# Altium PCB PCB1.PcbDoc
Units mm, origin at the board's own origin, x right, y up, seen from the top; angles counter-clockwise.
Board outline 89.28 x 76.58 mm, 2 copper layers (Top Layer, Bottom Layer); 90 components, 100 nets, 288 pads, 103 vias.
Unrouted connection lines stored in the file: 1.
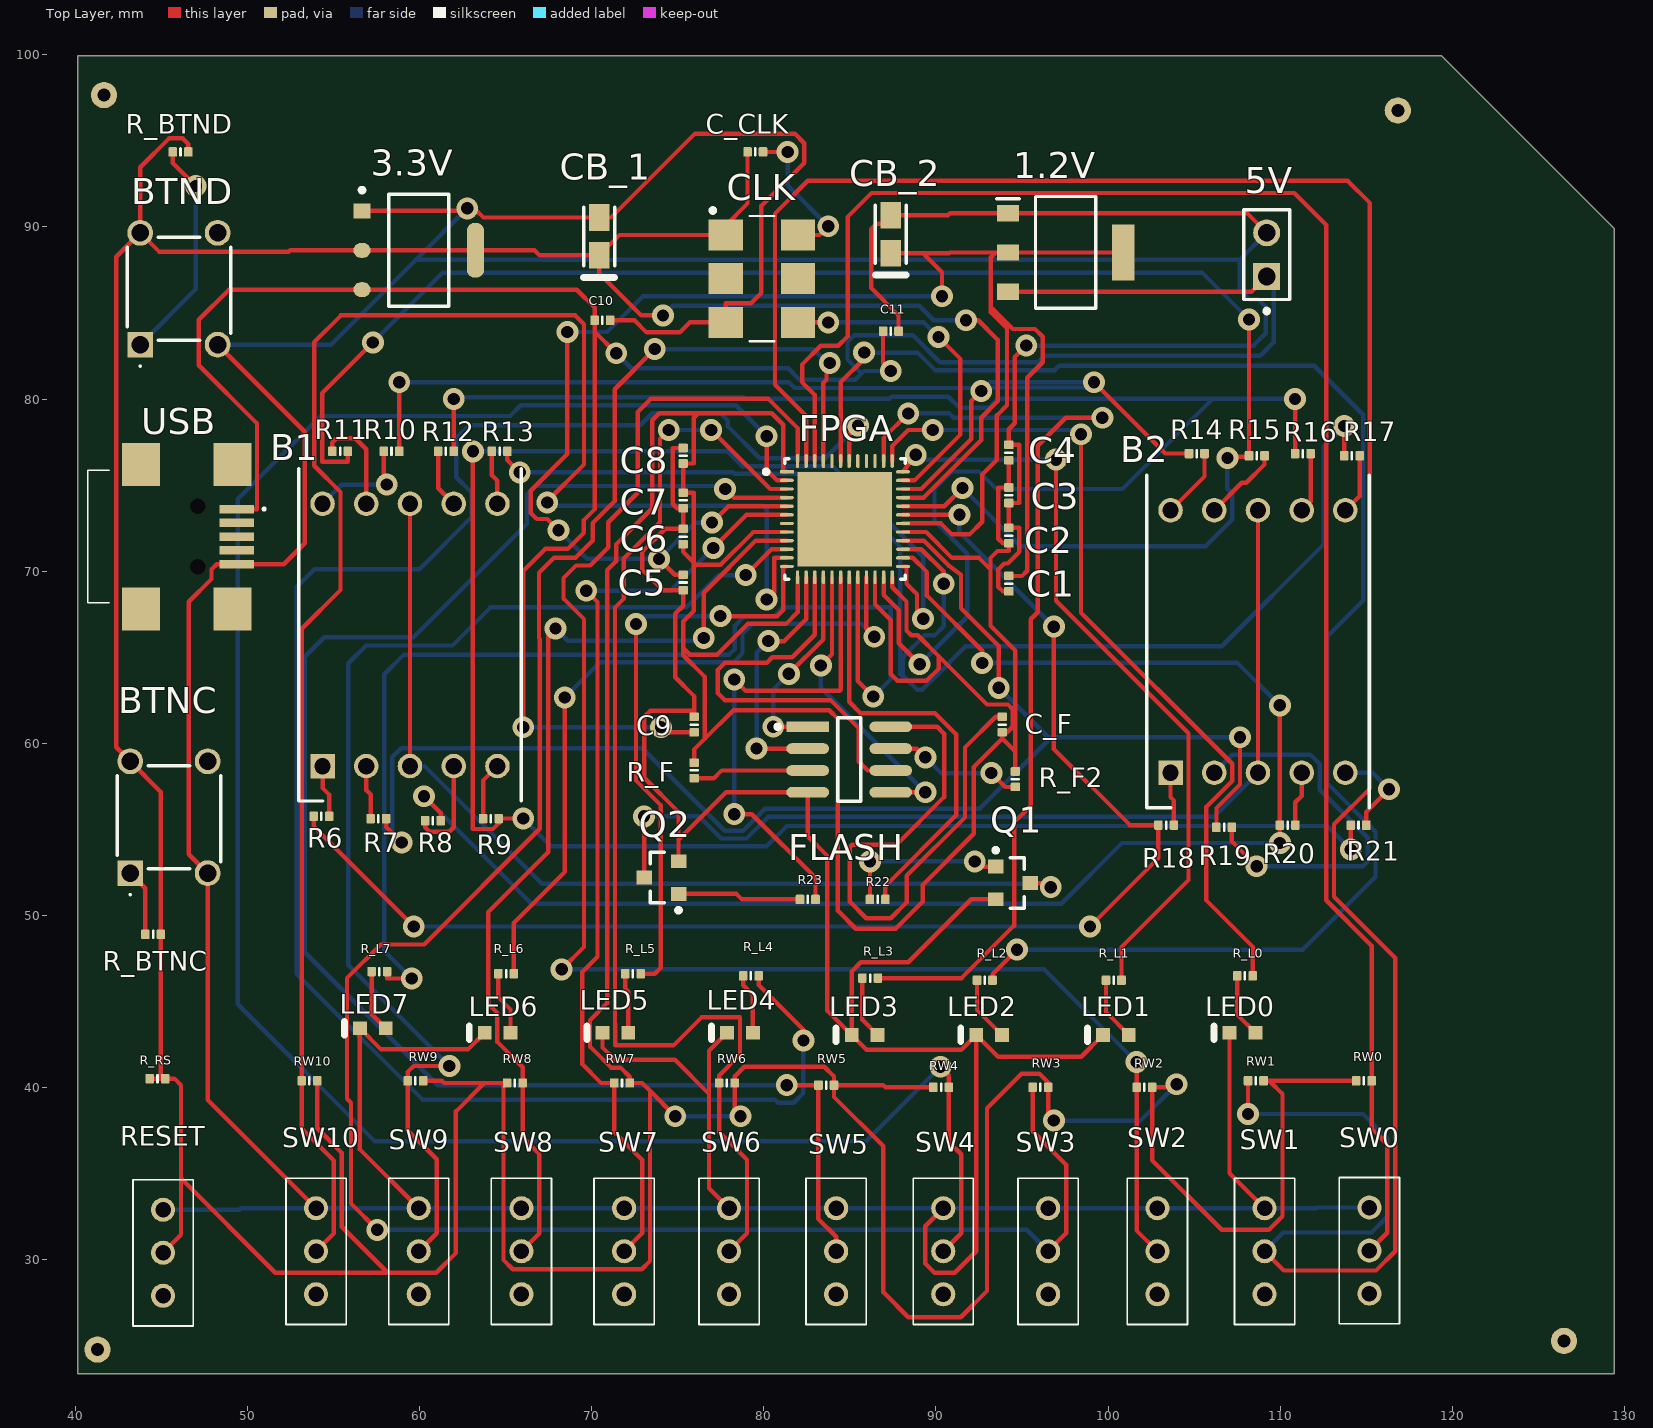
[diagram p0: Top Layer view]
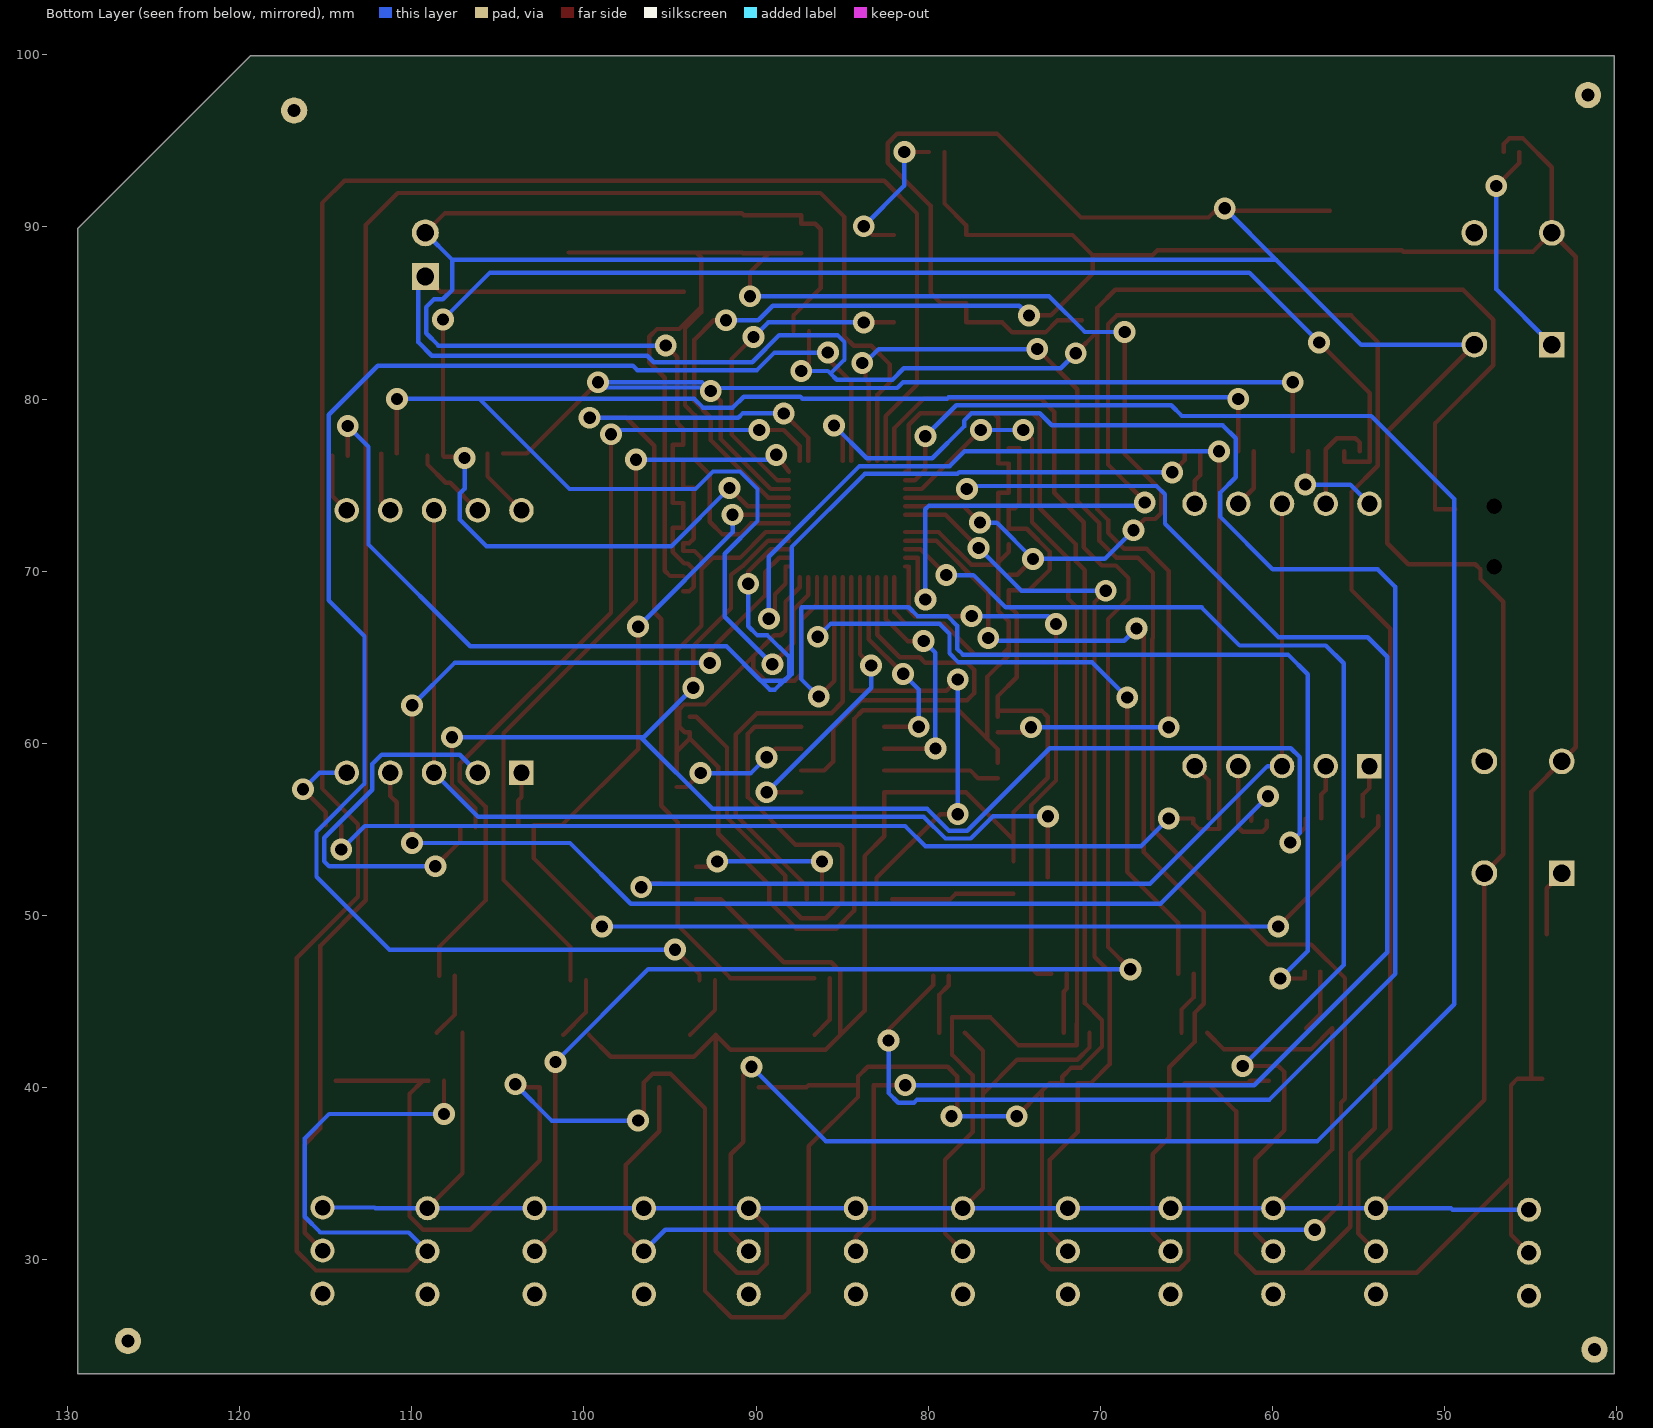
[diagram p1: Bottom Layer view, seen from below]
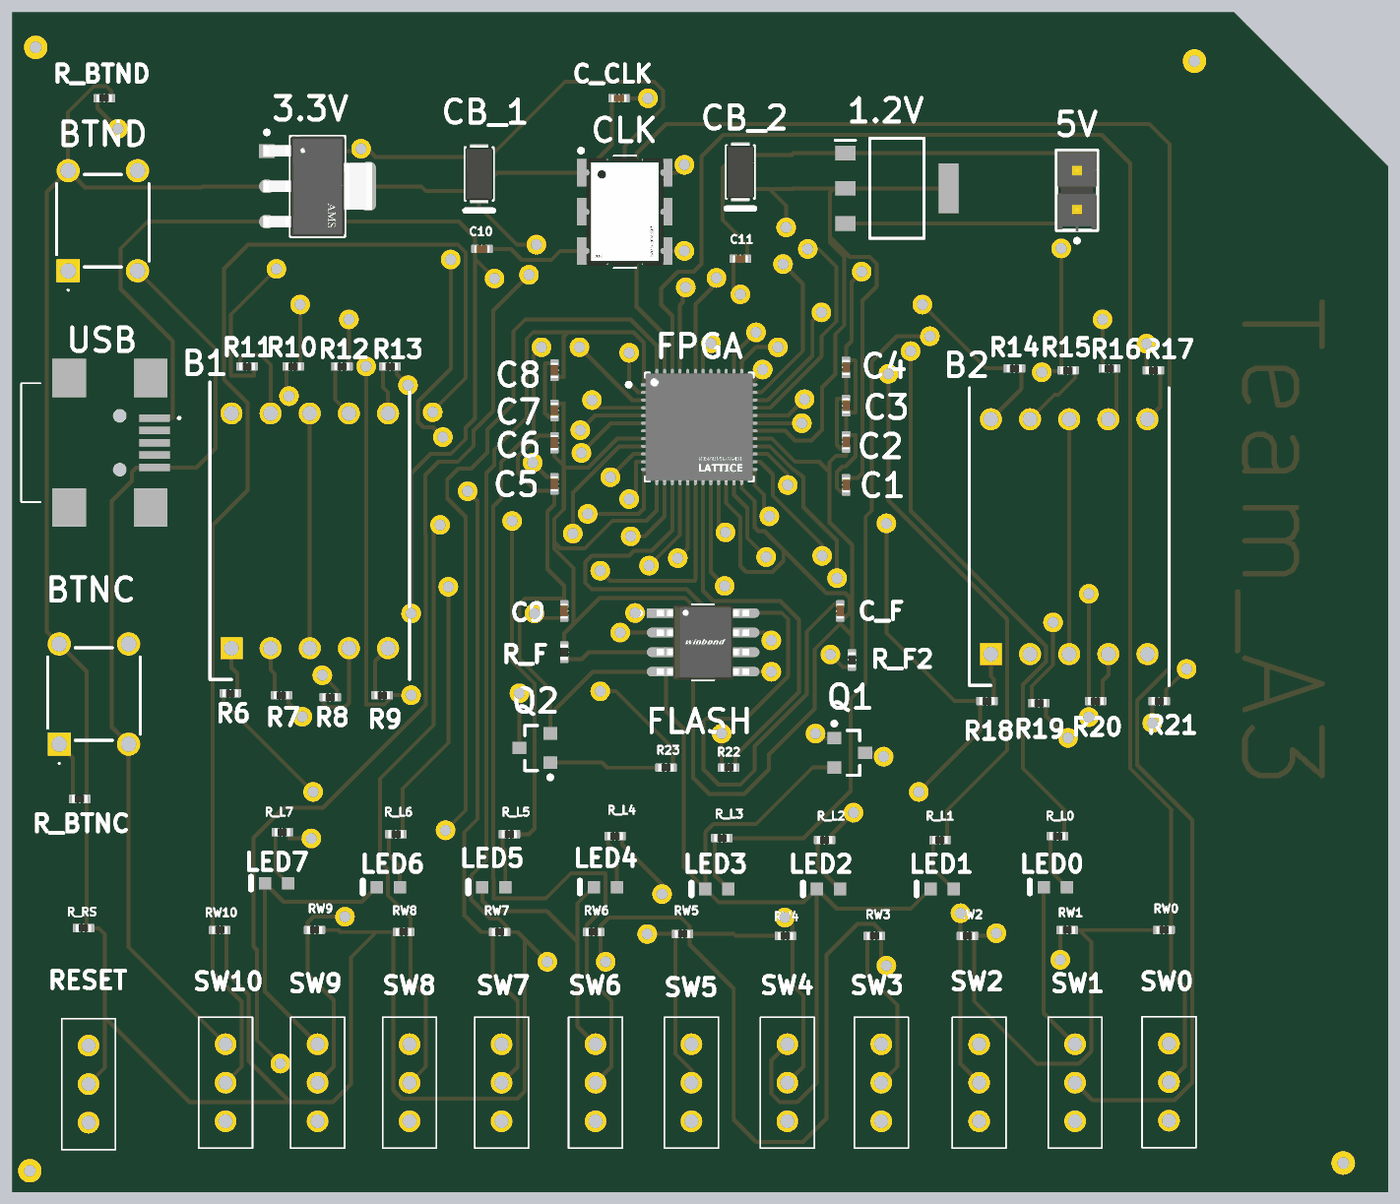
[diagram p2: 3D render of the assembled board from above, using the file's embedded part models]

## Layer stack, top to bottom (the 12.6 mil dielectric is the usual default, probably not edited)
Top Solder: solder mask 0.0102, Solder Resist, Dk 3.5
Top Layer: signal copper 0.0356
Dielectric 1: dielectric 0.32, FR-4, Dk 4.8
Bottom Layer: signal copper 0.0356
Bottom Solder: solder mask 0.0102, Solder Resist, Dk 3.5

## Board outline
40.132,23.368 40.132,99.949 119.38,99.949 129.413,89.916 129.413,23.368

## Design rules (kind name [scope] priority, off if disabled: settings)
Clearance [All] p1: gap=0.2 ignorepadtopadclearanceinfootprint=TRUE
HoleToHoleClearance [All] p1: gap=0.1 allowstackedmicrovias=TRUE
MinimumSolderMaskSliver [All] p1: minsoldermaskwidth=0.1
PolygonConnect [All] p1: connectstyle=Relief reliefconductorwidth=0.254 reliefentries=4 polygonreliefangle="90 Angle" airgapwidth=0.254
RoutingVias [All] p1: holewidth=0.711 width=1.27 viastyle="Through Hole" minholewidth=0.711 minwidth=1.27 maxholewidth=0.711 maxwidth=1.27
SilkToSilkClearance [All] p1 off: silktosilkclearance=0.254
SilkToSolderMaskClearance [IsPad] p1 off: minsilkscreentomaskgap=0.254 clearancetoexposedcopper=TRUE
SolderMaskExpansion [All] p1: expansion=0 istentingtop=FALSE
SupplyNets "Schematic Supply Nets_4" [InNet('VCC_1.2V')] p1: voltage=0.000
SupplyNets "Schematic Supply Nets_2" [InNet('GND')] p2: voltage=0.000
SupplyNets "Schematic Supply Nets" [InNet('VCC_3.3V')] p3: voltage=0.000
Width [All] p1: maxlimit=0.254 minlimit=0.254 preferedwidth=0.254
26 further rules are at their usual default settings.

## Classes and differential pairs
component class "Flash Memory_SPI": C_F FLASH R_F R_F2
component class Power_Supply: 1.2V 3.3V 5V C9 C10 C11 CB_1 CB_2 USB
component class FPGA: C1 C2 C3 C4 C5 C6 C7 C8 C_CLK CLK FPGA
component class 7Seg_&_Keypad: B1 B2 BTNC BTND LED0 LED1 LED2 LED3 LED4 LED5 LED6 LED7 Q1 Q2 R6 R7 R8 R9 R10 R11 R12 R13 R14 R15 R16 R17 R18 R19 R20 R21 R22 R23 R_BTNC R_BTND R_L0 R_L1 R_L2 R_L3 R_L4 R_L5 R_L6 R_L7 R_RS RESET RW0 RW1 RW2 RW3 RW4 RW5 RW6 RW7 RW8 RW9 RW10 SW0 SW1 SW2 SW3 SW4 SW5 SW6 SW7 SW8 SW9 SW10

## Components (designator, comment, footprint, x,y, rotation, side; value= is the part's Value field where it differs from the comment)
1.2V "AMS1117-1.2" SOT229P700X180-4N 97.536,88.519 r0 top
3.3V "AMS1117-3.3" FP-AMS1117-IPC_C 59.944,88.646 r0 top
5V "TSW-102-12-T-S" FP-TSW-102-12-T-S-MFG 109.22,88.392 r90 top
B1 "SC56-11EWA" DIPS1524W75P254L1270H825Q10N 54.356,58.674 r90 top
B2 "SC56-11EWA" DIPS1524W75P254L1270H825Q10N 103.632,58.293 r90 top
BTNC "1301.9301" 13019301 43.18,52.451 r90 top
BTND "1301.9301" 13019301 43.76,83.162 r90 top
C1 "Capacitor 100nF +/-20% 50V 0402" CAPC0402(1005)60_L 94.234,69.273 r270 top value=100nF
C2 "Capacitor 100nF +/-20% 50V 0402" CAPC0402(1005)60_L 94.234,72.067 r90 top value=100nF
C3 "Capacitor 100nF +/-20% 50V 0402" CAPC0402(1005)60_L 94.234,74.411 r270 top value=100nF
C4 "Capacitor 100nF +/-20% 50V 0402" CAPC0402(1005)60_L 94.234,76.893 r90 top value=100nF
C5 "Capacitor 100nF +/-20% 50V 0402" CAPC0402(1005)60_L 75.311,69.342 r270 top value=100nF
C6 "Capacitor 100nF +/-20% 50V 0402" CAPC0402(1005)60_L 75.311,72.009 r90 top value=100nF
C7 "Capacitor 100nF +/-20% 50V 0402" CAPC0402(1005)60_L 75.311,74.11 r270 top value=100nF
C8 "Capacitor 100nF +/-20% 50V 0402" CAPC0402(1005)60_L 75.311,76.708 r90 top value=100nF
C9 "Capacitor 100nF +/-20% 50V 0402" CAPC0402(1005)60_L 75.946,61.087 r90 top value=100nF
C10 "Capacitor 100nF +/-20% 50V 0402" CAPC0402(1005)60_L 70.612,84.582 r0 top value=100nF
C11 "Capacitor 100nF +/-20% 50V 0402" CAPC0402(1005)60_L 87.376,83.947 r0 top value=100nF
C_CLK "Capacitor 100nF +/-20% 25V 0402" CAPC0402(1005)60_L 79.502,94.361 r0 top value=100nF
C_F "Capacitor 100nF +/-20% 50V 0402" CAPC0402(1005)60_L 93.853,61.087 r90 top value=100nF
CB_1 "TAJA475K016RNJ" AVX-TAJ-A-2_L 70.427,89.451 r90 top value=4.7µF
CB_2 "TAJA475K016RNJ" AVX-TAJ-A-2_L 87.376,89.578 r90 top value=4.7µF
CLK "XLH735012.000000I" JU6_MFG 79.883,86.995 r0 top
FLASH "W25Q16JVSNIQ TR" FP-W25Q16JVSNIQ_TR-IPC_A 84.96,59.055 r0 top
FPGA "iCE40UP5K-SG48I" FP-QFN-48-IPC_C 84.709,73.025 r0 top
LED0 "19-217/Y5C-AM1N1VY/3T" EVRL-0603-2_V 107.811,43.18 r180 top
LED1 "19-217/Y5C-AM1N1VY/3T" EVRL-0603-2_V 100.457,43.053 r180 top
LED2 "19-217/Y5C-AM1N1VY/3T" EVRL-0603-2_V 93.091,43.053 r180 top
LED3 "19-217/Y5C-AM1N1VY/3T" EVRL-0603-2_V 85.852,43.053 r180 top
LED4 "19-217/Y5C-AM1N1VY/3T" EVRL-0603-2_V 78.613,43.18 r180 top
LED5 "19-217/Y5C-AM1N1VY/3T" EVRL-0603-2_V 71.374,43.18 r180 top
LED6 "19-217/Y5C-AM1N1VY/3T" EVRL-0603-2_V 64.528,43.18 r180 top
LED7 "19-217/Y5C-AM1N1VY/3T" EVRL-0603-2_V 57.277,43.434 r180 top
Q1 "SBC817-40LT3G" ONSC-SOT-23-3-318-08_V 94.472,51.882 r0 top
Q2 "SBC817-40LT3G" ONSC-SOT-23-3-318-08_V 74.041,52.197 r180 top
R6 "Resistor 330R +/-5 % 0402 63 mW" RESC0402(1005)_L 54.287,55.753 r0 top value=330
R7 "Resistor 330R +/-5 % 0402 63 mW" RESC0402(1005)_L 57.6,55.626 r180 top value=330
R8 "Resistor 330R +/-5 % 0402 63 mW" RESC0402(1005)_L 60.764,55.499 r180 top value=330
R9 "Resistor 330R +/-5 % 0402 63 mW" RESC0402(1005)_L 64.135,55.626 r180 top value=330
R10 "Resistor 330R +/-5 % 0402 63 mW" RESC0402(1005)_L 58.362,76.962 r0 top value=330
R11 "Resistor 330R +/-5 % 0402 63 mW" RESC0402(1005)_L 55.372,76.962 r0 top value=330
R12 "Resistor 330R +/-5 % 0402 63 mW" RESC0402(1005)_L 61.526,76.962 r0 top value=330
R13 "Resistor 330R +/-5 % 0402 63 mW" RESC0402(1005)_L 64.643,76.962 r0 top value=330
R14 "Resistor 330R +/-5 % 0402 63 mW" RESC0402(1005)_L 105.156,76.835 r180 top value=330
R15 "Resistor 330R +/-5 % 0402 63 mW" RESC0402(1005)_L 108.643,76.708 r180 top value=330
R16 "Resistor 330R +/-5 % 0402 63 mW" RESC0402(1005)_L 111.321,76.835 r180 top value=330
R17 "Resistor 330R +/-5 % 0402 63 mW" RESC0402(1005)_L 114.173,76.708 r180 top value=330
R18 "Resistor 330R +/-5 % 0402 63 mW" RESC0402(1005)_L 103.378,55.245 r0 top value=330
R19 "Resistor 330R +/-5 % 0402 63 mW" RESC0402(1005)_L 106.749,55.118 r0 top value=330
R20 "Resistor 330R +/-5 % 0402 63 mW" RESC0402(1005)_L 110.432,55.245 r0 top value=330
R21 "Resistor 330R +/-5 % 0402 63 mW" RESC0402(1005)_L 114.554,55.245 r0 top value=330
R22 "1KR2J" RESC0402(1005)_L 86.614,50.927 r180 top value=1k
R23 "1KR2J" RESC0402(1005)_L 82.55,50.927 r180 top value=1k
R_BTNC "10KR2F" RESC0402(1005)_L 44.508,48.895 r180 top value=10k
R_BTND "10KR2F" RESC0402(1005)_L 46.101,94.361 r180 top value=10k
R_F "10KR2F" RESC0402(1005)_L 75.946,58.42 r90 top value=10k
R_F2 "10KR2F" RESC0402(1005)_L 94.615,57.912 r90 top value=10k
R_L0 "330R2J" RESC0402(1005)_L 107.95,46.482 r180 top value=330
R_L1 "330R2J" RESC0402(1005)_L 100.33,46.228 r180 top value=330
R_L2 "330R2J" RESC0402(1005)_L 92.837,46.228 r180 top value=330
R_L3 "330R2J" RESC0402(1005)_L 86.175,46.355 r180 top value=330
R_L4 "330R2J" RESC0402(1005)_L 79.248,46.482 r180 top value=330
R_L5 "330R2J" RESC0402(1005)_L 72.39,46.609 r180 top value=330
R_L6 "330R2J" RESC0402(1005)_L 65.024,46.609 r180 top value=330
R_L7 "330R2J" RESC0402(1005)_L 57.658,46.736 r180 top value=330
R_RS "10KR2F" RESC0402(1005)_L 44.762,40.513 r0 top value=10k
RESET "SS12D00G3" SS12D00G3 45.085,30.393 r90 top
RW0 "10KR2F" RESC0402(1005)_L 114.866,40.386 r0 top value=10k
RW1 "10KR2F" RESC0402(1005)_L 108.585,40.386 r180 top value=10k
RW2 "10KR2F" RESC0402(1005)_L 102.108,40.005 r180 top value=10k
RW3 "10KR2F" RESC0402(1005)_L 96.07,40.005 r180 top value=10k
RW4 "10KR2F" RESC0402(1005)_L 90.297,40.005 r0 top value=10k
RW5 "10KR2F" RESC0402(1005)_L 83.624,40.132 r180 top value=10k
RW6 "10KR2F" RESC0402(1005)_L 77.851,40.259 r180 top value=10k
RW7 "10KR2F" RESC0402(1005)_L 71.755,40.259 r180 top value=10k
RW8 "10KR2F" RESC0402(1005)_L 65.532,40.259 r0 top value=10k
RW9 "10KR2F" RESC0402(1005)_L 59.748,40.386 r180 top value=10k
RW10 "10KR2F" RESC0402(1005)_L 53.594,40.386 r180 top value=10k
SW0 "SS12D00G3" SS12D00G3 115.189,30.52 r90 top
SW1 "SS12D00G3" SS12D00G3 109.093,30.48 r90 top
SW2 "SS12D00G3" SS12D00G3 102.87,30.48 r90 top
SW3 "SS12D00G3" SS12D00G3 96.52,30.48 r90 top
SW4 "SS12D00G3" SS12D00G3 90.424,30.48 r90 top
SW5 "SS12D00G3" SS12D00G3 84.201,30.48 r90 top
SW6 "SS12D00G3" SS12D00G3 77.978,30.48 r90 top
SW7 "SS12D00G3" SS12D00G3 71.882,30.48 r90 top
SW8 "SS12D00G3" SS12D00G3 65.913,30.48 r90 top
SW9 "SS12D00G3" SS12D00G3 59.944,30.48 r90 top
SW10 "SS12D00G3" SS12D00G3 53.975,30.48 r90 top
USB "UX60-MB-5ST" UX60MB5ST 45.212,72.009 r270 top

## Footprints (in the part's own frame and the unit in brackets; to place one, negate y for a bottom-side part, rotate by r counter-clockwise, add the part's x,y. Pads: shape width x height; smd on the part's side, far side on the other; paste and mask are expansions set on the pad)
13019301 [mm]
  rect 1.5x1.5 hole 1: 1(0,0)
  round 1.5 hole 1: 2(6.5,0) 3(0,-4.5) 4(6.5,-4.5)
  silkscreen extent -1.3,-5.25 6.25,0.75
AVX-TAJ-A-2_L [mm] "Molded Capacitor, 2-Leads, Body 3.4x1.8mm, IPC High Density"
  rect 1.55x1.2 smd: 1(-1.1,0) 2(1.1,0)
  silkscreen extent -2.38,-0.9 1.7,0.9, body extent -1.92,-0.9 1.92,0.9, height 1.8
CAPC0402(1005)60_L [mm] "Chip Capacitor, Body 1.0x0.5mm, Height 0.6mm, IPC High Density"
  rrect25% 0.5x0.55 smd: 1(-0.45,0) 2(0.45,0)
  silkscreen extent 0,-0.2 0,0.2, body extent -0.5,-0.25 0.5,0.25, height 0.6
DIPS1524W75P254L1270H825Q10N [mm]
  rect 1.425x1.425 / inner round 1.425 / far side rect 1.425x1.425 hole 0.95: 1(0,0)
  round 1.425 hole 0.95: 2(0,-2.54) 3(0,-5.08) 4(0,-7.62) 5(0,-10.16) 6(15.24,-10.16) 7(15.24,-7.62) 8(15.24,-5.08) 9(15.24,-2.54) 10(15.24,0)
  silkscreen extent -2.03,-11.56 17.27,1.4
EVRL-0603-2_V [mm] "SMD, 2-Leads, Body 1.6x0.8mm"
  rect 0.8x0.8 smd: 1(-0.75,0) 2(0.75,0)
  silkscreen extent 1.65,-0.4 1.65,0.4, body extent -0.8,-0.4 0.8,0.4, height 0.5
FP-AMS1117-IPC_C [mm]
  rect 1.004x0.872 smd paste+0 mask+0: 1(-3.295,2.29)
  rrect100% 1.004x0.872 smd paste+0 mask+0: 2(-3.295,0) 3(-3.295,-2.29)
  rrect87% 1.004x3.182 smd paste+0 mask+0: 4(3.295,0)
  silkscreen extent -3.42,-3.25 1.75,3.62, body extent -3.9,-3.35 3.9,3.35, height 0.25
FP-QFN-48-IPC_C [mm]
  rect 0.808x0.192 smd paste+0 mask+0: 1(-3.375,2.75)
  rrect100% 0.808x0.192 smd paste+0 mask+0: 2(-3.375,2.25) 3(-3.375,1.75) 4(-3.375,1.25) 5(-3.375,0.75) 6(-3.375,0.25) 7(-3.375,-0.25) 8(-3.375,-0.75) 9(-3.375,-1.25) 10(-3.375,-1.75) 11(-3.375,-2.25) 12(-3.375,-2.75) 25(3.375,-2.75) 26(3.375,-2.25) 27(3.375,-1.75) 28(3.375,-1.25) 29(3.375,-0.75) 30(3.375,-0.25) 31(3.375,0.25) 32(3.375,0.75) 33(3.375,1.25) 34(3.375,1.75) 35(3.375,2.25) 36(3.375,2.75)
  rrect100% 0.192x0.808 smd paste+0 mask+0: 13(-2.75,-3.375) 14(-2.25,-3.375) 15(-1.75,-3.375) 16(-1.25,-3.375) 17(-0.75,-3.375) 18(-0.25,-3.375) 19(0.25,-3.375) 20(0.75,-3.375) 21(1.25,-3.375) 22(1.75,-3.375) 23(2.25,-3.375) 24(2.75,-3.375) 37(2.75,3.375) 38(2.25,3.375) 39(1.75,3.375) 40(1.25,3.375) 41(0.75,3.375) 42(0.25,3.375) 43(-0.25,3.375) 44(-0.75,3.375) 45(-1.25,3.375) 46(-1.75,3.375) 47(-2.25,3.375) 48(-2.75,3.375)
  rect 5.5x5.5 smd paste-1000 mask+0: 49(0,0)
  silkscreen extent -4.7,-3.5 3.5,3.5, body extent -3.88,-3.88 3.88,3.88, height 0.25
FP-TSW-102-12-T-S-MFG [mm]
  rect 1.57x1.57 hole 1.02 paste-2539.97 mask+0: 1(-1.27,0)
  round 1.57 hole 1.02 paste-2539.97 mask+0: 2(1.27,0)
  silkscreen extent -3.4,-1.34 2.61,1.34, body extent -2.71,-1.44 2.71,1.44, height 0.25
FP-W25Q16JVSNIQ_TR-IPC_A [mm]
  rect 2.474x0.623 smd paste+0 mask+0: 1(-2.416,1.905)
  rrect100% 2.474x0.623 smd paste+0 mask+0: 2(-2.416,0.635) 3(-2.416,-0.635) 4(-2.416,-1.905) 5(2.416,-1.905) 6(2.416,-0.635) 7(2.416,0.635) 8(2.416,1.905)
  silkscreen extent -4.28,-2.42 0.68,2.42, body extent -4.15,-2.93 4.15,2.93, height 0.25
JU6_MFG [mm] "Recommended Land Pattern"
  rect 2x1.8 smd paste+0 mask+0: 1(-2.1,2.54) 2(-2.1,0) 3(-2.1,-2.54) 4(2.1,-2.54) 5(2.1,0) 6(2.1,2.54)
  silkscreen extent -2.97,-3.64 0.73,4.09, body extent -2.5,-3.5 2.5,3.5, height 1.45
ONSC-SOT-23-3-318-08_V [mm] "SOT23, 3-Leads, Body 2.92x1.3mm, Pitch 0.95mm"
  rect 0.9x0.8 smd: 1(-1,0.95) 2(-1,-0.95) 3(1,0)
  silkscreen extent -1.12,-1.46 0.65,2.02, body extent -0.65,-1.46 0.65,1.46, height 1.11
RESC0402(1005)_L [mm] "Chip Resistor, Body 1.0x0.5mm, IPC High Density"
  rrect25% 0.5x0.55 smd: 1(-0.45,0) 2(0.45,0)
  silkscreen extent 0,-0.2 0,0.2, body extent -0.5,-0.25 0.5,0.25, height 0.3
SOT229P700X180-4N [mm]
  rect 1.3x0.95 smd: 1(-3.35,2.29) 2(-3.35,0) 3(-3.35,-2.29)
  rect 1.3x3.25 smd: 4(3.35,0)
  silkscreen extent -4,-3.25 1.75,3.25
SS12D00G3 [mm]
  round 1.4 hole 0.9: 1(-2.5,0) 2(0,0) 3(2.5,0)
  silkscreen extent -4.25,-1.75 4.25,1.75
UX60MB5ST [mm]
  rect 0.5x2 smd: 1(-1.6,4.15) 2(-0.8,4.15) 3(0,4.15) 4(0.8,4.15) 5(1.6,4.15)
  round 0.45 hole 0.9 unplated: MH1(-1.75,1.9) MH2(1.75,1.9)
  rect 2.5x2.2 smd: MP1(-4.2,3.9) MP2(4.2,3.9) MP3(-4.2,-1.4) MP4(4.2,-1.4)
  silkscreen extent -3.85,-4.5 3.85,5.8

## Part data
1.2V: "Descriptions of ams AMS1117-1.2 provided by its distributors.", Manufacturer_Name="Advanced Monolithic Systems"
3.3V: library part CMP-209535-000001-1, "LDO Voltage Regulators 1A, 3.3V", Dropout Voltage=1.1V, Manufacturer="Advanced Monolithic Systems", Max Junction Temp=+125°C, Max Power Dissipation=1.2W, Max Supply Voltage=15V, Nominal Supply Current=5mA, Output Current=1A, Output Voltage=3.3V, Package=AMS1117, Temperature="-40°C to +125°C", Temperature Range Low=-40°C
5V: library part CMP-02766-001444-1, "CONN HEADER VERT 2POS 2.54MM"
B1 B2: "Display Modules - LED Character and Numeric Red 7-Segment 1 Character Common Cathode 2V 20mA 0.750\" H x 0.500\" W x 0.315\" D (19.05mm x 12.70mm x 8.00mm) 10-DIP (0.600\", 15.24mm)", Manufacturer_Name=Kingbright, Mouser Part Number=604-SC56-11EWA
BTNC BTND: "LPH 4.3mm 3.4mm bulk material standard", Manufacturer_Name=SCHURTER, Mouser Part Number=693-1301.9301
C1 C2 C3 C4 C5 C6 C7 C8 C9 C10 C11 C_F: library part CMP-001-00067-3, "Chip Capacitor, 100nF +/-20%, 50V, 0402, Thickness 0.6 mm", Case/Package=0402, Max Operating Temperature=85°C, Min Operating Temperature=-55°C, Tolerance=10%, Voltage Rating=50V
C_CLK: library part CMP-001-00065-4, "Chip Capacitor, 100nF +/-20%, 25V, 0402, Thickness 0.6 mm", Case/Package=0402, Max Operating Temperature=85°C, Min Operating Temperature=-55°C, Tolerance=10%, Voltage Rating=25V
CB_1 CB_2: library part CMP-001-00042-7, "Standard Tantalum, 4.7 uF, +/- 10%, 16 V, -55 to 125 degC, 1206 (3216 Metric), RoHS, Tape and Reel", Capacitor Type=Tantalum, Case/Package=1206, Manufacturer=AVX, Max Operating Temperature=125°C, Min Operating Temperature=-55°C, Package Description="2-Pin Surface Mount Device, Body 3.2 x 1.65 mm", Package Quantity=2000, Package Reference=TAJ-A-2, Resistance=4Ohm, Tolerance=10%, Voltage Rating=16V
CLK: library part CMP-00572-106940963-3, "XO, 12.0 MHz, 1, 000 fs jitter, LVCMOS, 3.3 V, ±50 ppm, ‐40 to +85 °C, 7.0 x 5.0 mm", Case/Package=CLCC, Max Input Voltage=3.465V, Max Operating Temperature=85°C, Max Output Frequency=99.9MHz, Min Input Voltage=3.135V, Min Operating Temperature=-40°C
FLASH: library part CMP-78876-000009-2, "IC FLASH 16MBIT SPI/QUAD 8SOIC", Ambient Temperature Range High=85°C, Max Supply Voltage=3.6V, Min Operating Temperature=-40°C, Min Supply Voltage=2.7V
FPGA: library part CMP-17932-000001-1, "ICE40-ULTRAPLUS, 5280 LUTS, 1.2V", Frequency=48MHz, Manufacturer=Lattice, Max Junction Temp=+100°C, Max Supply Voltage=3.46V, Min Supply Voltage=1.14V, Nominal Supply Current=2.5-12mA, Package=QFN-48, Temperature="-40°C to +100°C", Temperature Range Low=-40°C
LED0 LED1 LED2 LED3 LED4 LED5 LED6 LED7: library part CMP-007-00005-2, "Chip LED, Yellow, 5 V, 25mA, -40 to 85 degC, 2-Pin SMD (0603), RoHS, Tape and Reel", Case/Package=0603, Manufacturer="Everlight Electronics", Package Description="2-Pin Surface Mount Device, Body 1.6 x 0.8 mm"
Q1 Q2: library part CMP-1048-00776-1, "General Purpose Transistor, NPN Silicon, 3-Pin SOT-23, Pb-Free, Tape and Reel", Manufacturer="On Semiconductor"
R6 R7 R8 R9 R10 R11 R12 R13 R14 R15 R16 R17 R18 R19 R20 R21: library part CMP-009-00132-3, "Chip Resistor, 330 Ohms, +/-5 %, 63 mW, -55 to 155 degC, 0402", Case/Package=0402, Max Operating Temperature=155°C, Min Operating Temperature=-55°C, Power=63mW, Tolerance=5%
R22 R23: library part CMP-009-00075-2, "1K 0.063W 5% 0402 (1005 Metric)  SMD", Case/Package=0402, Power=63mW, Tolerance=5%
R_BTNC R_BTND R_F R_F2 R_RS RW0 RW1 RW2 RW3 RW4 RW5 RW6 RW7 RW8 RW9 RW10: library part CMP-009-00066-2, "10K 0.063W 1% 0402 (1005 Metric)  SMD", Case/Package=0402, Power=63mW, Tolerance=1%
R_L0 R_L1 R_L2 R_L3 R_L4 R_L5 R_L6 R_L7: library part CMP-009-00095-2, "330R 0.063W 5% 0402 (1005 Metric)  SMD", Case/Package=0402, Power=63mW, Tolerance=5%
RESET SW0 SW1 SW2 SW3 SW4 SW5 SW6 SW7 SW8 SW9 SW10: "3 Pin Toggle Switch", Manufacturer_Name=Vimex
USB: "USB Connectors MINI B RECEPT RA SMT W/ POST", Manufacturer_Name=Hirose, Mouser Part Number=798-UX60-MB-5ST

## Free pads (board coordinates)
  round 1.524 hole 0.762: 3(41.656,97.663) 4(41.275,24.765) 5(126.492,25.273) 6(116.84,96.774)

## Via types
v1: diameter 1.27, hole 0.711, Top Layer to Bottom Layer, 103 vias

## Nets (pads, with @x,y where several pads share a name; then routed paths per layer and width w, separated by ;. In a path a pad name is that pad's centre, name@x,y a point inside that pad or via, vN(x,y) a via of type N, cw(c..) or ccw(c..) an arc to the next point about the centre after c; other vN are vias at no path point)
CLK_12M: CLK.4 FPGA.35 | length 19.1
  Top Layer w0.254: CLK.4 v1(83.744,84.455) ; FPGA.35 88.752,75.275 91.419,77.942 91.419,82.326 v1(90.144,83.601)
  Bottom Layer w0.254: v1(83.744,84.455) 89.29,84.455 v1(90.144,83.601)
DIGIT_1: FPGA.19 R22.1 | length 25.5
  Top Layer w0.254: FPGA.19 84.959,62.407 85.619,61.747 89.941,61.747 91.171,60.518 91.171,55.814 87.064,51.707 R22.1
DIGIT_2: FPGA.18 R23.1 | length 28.3
  Top Layer w0.254: v1(78.283,55.88) 79.299,55.88 83,52.179 R23.1 ; v1(78.283,63.703) 78.937,63.049 84.405,63.049 84.459,63.103 FPGA.18
  Bottom Layer w0.254: v1(78.283,55.88) v1(78.283,63.703)
FLASH_SCK: FLASH.6 FPGA.15 | length 24.2
  Top Layer w0.254: FPGA.15 82.959,66.311 81.647,64.999 80.493,64.999 80.162,64.668 77.724,64.668 77.318,64.262 77.318,62.916 77.724,62.509 83.871,62.509 85.522,60.858 85.522,58.928 86.03,58.42 FLASH.6
FLASH_SI: FLASH.5 FPGA.17 | length 17.3
  Top Layer w0.254: v1(83.312,64.519) 83.959,65.166 FPGA.17 ; FLASH.5 v1(89.383,57.15)
  Bottom Layer w0.254: v1(83.312,64.519) 83.312,63.221 v1(89.383,57.15)
FLASH_SO: FLASH.2 FPGA.14 | length 14.7
  Top Layer w0.254: v1(79.578,59.69) FLASH.2 ; v1(80.261,65.938) 81.182,65.938 82.459,67.215 FPGA.14
  Bottom Layer w0.254: v1(79.578,59.69) 79.578,65.256 v1(80.261,65.938)
FLASH_SS: FLASH.1 FPGA.16 | length 11.9
  Top Layer w0.254: v1(80.543,60.96) FLASH.1 ; v1(81.452,64.033) 83.459,66.04 FPGA.16
  Bottom Layer w0.254: v1(80.543,60.96) 80.543,63.124 v1(81.452,64.033)
GND: 1.2V.1 3.3V.1 5V.2 BTNC.3 BTND.3 C1.2 C2.2 C3.2 C4.2 C5.2 C6.2 C7.2 C8.2 C9.2 C10.2 C11.2 CB_1.2 CB_2.2 CLK.3 FLASH.4 FPGA.49 LED0.2 LED1.2 LED2.2 LED3.2 LED4.2 LED5.2 LED6.2 LED7.2 Q1.2 Q2.2 RESET.3 SW0.3 SW1.3 SW2.3 SW3.3 SW4.3 SW5.3 SW6.3 SW7.3 SW8.3 SW9.3 SW10.3 USB.5 | length 472
  Top Layer w0.254: BTND.3 53.315,78.107 53.315,71.628 52.096,70.409 USB.5 48.209,70.409 47.904,70.104 47.904,69.545 46.584,68.224 46.584,53.547 BTNC.3 47.68,39.275 SW10.3 ; 3.3V.1 v1@62.615,90.936 ; SW9.3 56.527,36.397 LED7.2 57.749,42.212 62.81,42.212 LED6.2 ; v1(62.763,91.084) v1@62.615,90.936 ; LED5.2 70.624,42.318 71.337,41.605 74.828,41.605 76.81,39.624 ; C10.2 72.481,84.582 73.187,83.876 75.111,83.876 75.689,84.455 CLK.3 77.783,85.573 79.248,85.573 79.858,86.182 79.858,91.237 82.347,93.726 82.347,94.869 81.788,95.428 75.997,95.428 71.12,90.551 CB_1.2 63.707,90.551 63.322,90.936 v1@62.615,90.936 ; Q2.2 75.041,54.391 ; C8.2 74.701,77.158 74.701,73.914 74.955,73.66 C7.2 C6.2 74.263,72.459 72.924,71.12 72.924,70.104 74.136,68.892 C5.2 75.311,67.991 74.857,67.537 74.857,63.83 75.946,62.741 75.946,61.9 ; C9.2 75.946,61.9 ; LED4.2 76.81,42.127 76.81,39.624 ; SW6.3 76.81,34.148 76.81,39.624 ; C11.2 87.826,84.861 86.233,86.454 86.233,89.864 86.563,90.194 87.376,90.194 CB_2.2 90.703,90.678 90.834,90.809 1.2V.1 108.073,90.809 5V.2 ; SW4.3 89.383,31.939 89.383,29.769 89.916,29.235 91.096,29.235 92.341,30.48 LED2.2 ; Q1.2 92.055,50.932 88.392,47.269 85.635,47.269 85.102,46.736 LED3.2 ; C1.2 93.889,68.823 93.624,69.088 93.624,70.104 93.967,70.447 94.171,70.447 94.844,71.12 94.844,72.517 C2.2 C3.2 94.844,73.961 94.844,77.343 C4.2 94.234,78.251 94.58,78.597 94.58,82.439 v1(95.25,83.109) ; LED1.2 98.437,41.783 93.611,41.783 LED2.2 ; LED0.2 107.061,35.012 SW1.3 ; 75.041,54.391 75.041,56.007 73.05,57.998 73.05,61.544 73.406,61.9 75.946,61.9 ; 75.041,54.391 77.8,57.15 FLASH.4 82.544,54.591 83.693,53.442 83.693,44.462 LED3.2 ; LED3.2 85.966,42.189 91.477,42.189 LED2.2
  Bottom Layer w0.254: RESET.3 49.53,32.893 49.617,32.98 SW10.3 SW9.3 SW8.3 SW7.3 SW6.3 SW5.3 SW4.3 SW3.3 SW2.3 SW1.3 112.116,32.98 112.156,33.02 SW0.3 ; BTND.3 54.841,83.162 59.766,88.087 ; v1(62.763,91.084) 59.766,88.087 ; v1(95.25,83.109) 108.458,83.109 109.169,83.82 109.169,85.344 108.712,85.801 108.204,85.801 107.645,86.36 107.645,88.087 ; 5V.2 107.645,88.087 ; 59.766,88.087 107.645,88.087
LED0: FPGA.37 R_L0.1 | length 49.2
  Top Layer w0.254: FPGA.37 87.459,77.274 88.392,78.207 v1(89.814,78.207) ; v1(98.425,77.953) 98.425,67.589 107.212,58.803 107.212,57.809 105.715,56.312 105.715,50.869 108.4,48.184 R_L0.1
  Bottom Layer w0.254: v1(89.814,78.207) 98.171,78.207 v1(98.425,77.953)
LED1: FPGA.36 R_L1.1 | length 44.6
  Top Layer w0.254: FPGA.36 88.087,75.775 v1(88.824,76.759) ; v1(96.977,76.479) 96.977,68.275 104.673,60.579 104.673,52.052 100.78,48.158 R_L1.1
  Bottom Layer w0.254: v1(88.824,76.759) 89.103,76.479 v1(96.977,76.479)
LED2: FPGA.43 R_L2.1 | length 91.4
  Top Layer w0.254: FPGA.43 84.459,80.975 85.827,82.343 v1(85.827,82.702) ; R_L2.1 93.287,46.576 v1(94.717,48.006)
  Bottom Layer w0.254: v1(85.827,82.702) 88.925,82.702 89.941,81.686 96.901,81.686 97.155,81.94 111.989,81.94 114.833,79.096 114.833,68.301 112.752,66.22 112.752,57.656 115.545,54.864 115.545,52.248 111.303,48.006 v1(94.717,48.006)
LED3: FPGA.38 R_L3.1 | length 56.8
  Top Layer w0.254: R_L3.1 91.491,46.355 94.539,49.403 94.539,55.397 95.504,56.363 95.504,67.208 95.91,67.615 95.91,77.292 97.536,78.918 v1(99.67,78.918) ; FPGA.38 86.959,77.736 v1(88.392,79.169)
  Bottom Layer w0.254: v1(88.392,79.169) 90.78,79.169 91.03,78.918 v1(99.67,78.918)
LED4: FPGA.42 R_L4.1 | length 108.2
  Top Layer w0.254: R_L4.1 79.698,45.95 82.296,43.352 v1(82.296,42.723) ; FPGA.42 84.959,77.953 v1(85.467,78.461)
  Bottom Layer w0.254: v1(82.296,42.723) 82.296,39.675 81.737,39.116 80.823,39.116 80.645,39.294 60.16,39.294 52.857,46.596 52.857,69.088 53.873,70.104 59.969,70.104 63.017,73.152 63.017,74.574 62.128,75.463 62.128,77.724 62.89,78.486 72.823,78.486 73.508,79.17 77.479,79.17 77.909,78.74 77.909,78.406 79.756,76.559 83.565,76.559 v1(85.467,78.461)
LED5: FPGA.12 R_L5.1 | length 33.5
  Top Layer w0.254: v1(72.568,66.929) 72.568,57.836 74.016,56.388 74.016,46.965 73.66,46.609 R_L5.1 ; v1(77.47,67.389) 80.772,67.389 81.124,67.742 81.124,70.275 FPGA.12
  Bottom Layer w0.254: v1(72.568,66.929) 73.028,67.389 v1(77.47,67.389)
LED6: FPGA.21 R_L6.1 | length 41.6
  Top Layer w0.254: R_L6.1 65.474,49.572 68.428,52.526 v1(68.428,62.662) ; FPGA.21 85.959,66.644 v1(86.411,66.192)
  Bottom Layer w0.254: v1(68.428,62.662) 70.466,64.7 78.232,64.7 78.759,65.227 78.759,66.365 79.329,66.935 85.668,66.935 v1(86.411,66.192)
LED7: FPGA.20 R_L7.1 | length 64.9
  Top Layer w0.254: R_L7.1 58.108,46.331 v1(59.538,46.331) ; FPGA.20 85.459,67.165 85.449,67.154 85.449,63.624 v1(86.36,62.713)
  Bottom Layer w0.254: v1(59.538,46.331) 57.942,47.927 57.942,64.008 59.089,65.154 77.978,65.154 78.305,65.481 78.305,66.819 78.875,67.389 80.616,67.389 81.124,67.897 87.341,67.897 87.383,67.855 87.383,63.736 v1(86.36,62.713)
NetB1_1: B1.1 R6.2 | length 3.1
  Top Layer w0.254: B1.1 54.356,57.404 54.737,57.023 R6.2
NetB1_2: B1.2 R7.2 | length 3.2
  Top Layer w0.254: B1.2 56.896,57.277 57.15,57.023 R7.2
NetB1_4: B1.4 R8.2 | length 5.8
  Top Layer w0.254: R8.2 60.314,55.118 60.568,54.864 61.722,54.864 61.976,55.118 B1.4
NetB1_5: B1.5 R9.2 | length 3.4
  Top Layer w0.254: R9.2 63.685,57.843 B1.5
NetB1_6: B1.6 R13.1 | length 3.2
  Top Layer w0.254: R13.1 64.193,75.583 64.516,75.26 B1.6
NetB1_7: B1.7 R12.1 | length 3.4
  Top Layer w0.254: R12.1 61.076,74.814 B1.7
NetB1_9: B1.9 R11.1 | length 6
  Top Layer w0.254: R11.1 54.922,77.47 55.176,77.724 56.261,77.724 56.896,77.089 B1.9
NetB1_10: B1.10 R10.1 | length 6.2
  Top Layer w0.254: R10.1 57.912,75.209 v1(58.09,75.032)
  Bottom Layer w0.254: B1.10 55.474,75.032 v1(58.09,75.032)
NetB2_1: B2.1 R18.2 | length 3.1
  Top Layer w0.254: B2.1 103.632,56.863 103.828,56.667 R18.2
NetB2_2: B2.2 R19.2 | length 23
  Top Layer w0.254: R19.2 107.199,54.294 v1(108.636,52.857)
  Bottom Layer w0.254: B2.2 107.213,59.334 111.76,59.334 112.298,58.796 112.298,57.294 115.087,54.505 115.087,53.137 114.808,52.857 v1(108.636,52.857)
NetB2_4: B2.4 R20.2 | length 3.2
  Top Layer w0.254: R20.2 110.882,56.566 111.252,56.936 B2.4
NetB2_5: B2.5 R21.2 | length 5.6
  Top Layer w0.254: R21.2 115.004,56 v1(116.332,57.328)
  Bottom Layer w0.254: B2.5 115.367,58.293 v1(116.332,57.328)
NetB2_6: B2.6 R17.1 | length 3.5
  Top Layer w0.254: B2.6 114.623,74.364 R17.1
NetB2_7: B2.7 R16.1 | length 3.5
  Top Layer w0.254: B2.7 111.771,74.052 R16.1
NetB2_9: B2.9 R15.1 | length 4.5
  Top Layer w0.254: B2.9 107.772,75.133 108.026,75.133 109.093,76.2 R15.1
NetB2_10: B2.10 R14.1 | length 4.1
  Top Layer w0.254: B2.10 105.606,75.507 R14.1
NetBTNC_1: BTNC.1 R_BTNC.2 | length 3.9
  Top Layer w0.254: BTNC.1 44.058,51.573 R_BTNC.2
NetBTNC_4: BTNC.4
NetBTND_1: BTND.1 R_BTND.2 | length 13.1
  Top Layer w0.254: R_BTND.2 45.651,93.719 v1(46.99,92.38)
  Bottom Layer w0.254: BTND.1 46.99,86.392 v1(46.99,92.38)
NetBTND_4: BTND.4
NetC_CLK_2: C_CLK.2 CLK.6 | length 8.7
  Top Layer w0.254: C_CLK.2 v1(81.382,94.361) ; CLK.6 83.236,89.535 v1(83.744,90.043)
  Bottom Layer w0.254: v1(81.382,94.361) 81.382,92.405 v1(83.744,90.043)
NetC_F_2: C_F.2 FLASH.8 | length 34.2
  Top Layer w0.254: FLASH.8 90.068,60.96 90.475,60.554 90.475,56.871 87.71,54.106 85.14,54.106 84.988,53.955 84.988,50.8 85.953,49.835 87.376,49.835 88.295,50.754 88.295,52.296 91.691,55.692 91.691,59.756 93.472,61.537 C_F.2
NetCLK_2: CLK.2
NetCLK_5: CLK.5
NetFLASH_3: FLASH.3 R_F.1 | length 6.8
  Top Layer w0.254: R_F.1 77.095,57.97 77.545,58.42 FLASH.3
NetFLASH_7: FLASH.7 R_F2.1 | length 8.2
  Top Layer w0.254: FLASH.7 88.875,59.69 v1(89.383,59.182) ; v1(93.218,58.268) 94.024,57.462 R_F2.1
  Bottom Layer w0.254: v1(89.383,59.182) 90.297,58.268 v1(93.218,58.268)
NetFPGA_7: FPGA.7
NetFPGA_39: FPGA.39
NetFPGA_40: FPGA.40
NetFPGA_41: FPGA.41
NetFPGA_44: FPGA.44
NetLED0_1: LED0.1 R_L0.2 | length 3.7
  Top Layer w0.254: R_L0.2 107.5,44.241 LED0.1
NetLED1_1: LED1.1 R_L1.2 | length 3.7
  Top Layer w0.254: R_L1.2 99.88,44.38 LED1.1
NetLED2_1: LED2.1 R_L2.2 | length 3.8
  Top Layer w0.254: R_L2.2 92.387,44.507 LED2.1
NetLED3_1: LED3.1 R_L3.2 | length 3.7
  Top Layer w0.254: R_L3.2 85.725,43.93 LED3.1
NetLED4_1: LED4.1 R_L4.2 | length 3.5
  Top Layer w0.254: R_L4.2 78.798,45.942 79.363,45.377 LED4.1
NetLED5_1: LED5.1 R_L5.2 | length 3.5
  Top Layer w0.254: R_L5.2 71.94,45.75 72.124,45.566 LED5.1
NetLED6_1: LED6.1 R_L6.2 | length 3.7
  Top Layer w0.254: R_L6.2 64.574,45.23 65.278,44.526 LED6.1
NetLED7_1: LED7.1 R_L7.2 | length 3.6
  Top Layer w0.254: R_L7.2 57.208,44.253 LED7.1
NetQ1_1: Q1.1 R22.2 | length 9.6
  Top Layer w0.254: R22.2 v1(86.164,53.137) ; v1(92.253,53.137) 92.558,52.832 Q1.1
  Bottom Layer w0.254: v1(86.164,53.137) v1(92.253,53.137)
NetQ2_1: Q2.1 R23.2 | length 7.2
  Top Layer w0.254: Q2.1 78.41,51.247 78.73,50.927 R23.2
NetRESET_1: RESET.1
NetSW0_1: SW0.1
NetSW1_1: SW1.1
NetSW2_1: SW2.1
NetSW3_1: SW3.1
NetSW4_1: SW4.1
NetSW5_1: SW5.1
NetSW6_1: SW6.1
NetSW7_1: SW7.1
NetSW8_1: SW8.1
NetSW9_1: SW9.1
NetSW10_1: SW10.1
NetUSB_2: USB.2
NetUSB_3: USB.3
NetUSB_4: USB.4
NetUSB_MP1: USB.MP1
NetUSB_MP2: USB.MP2
NetUSB_MP3: USB.MP3
NetUSB_MP4: USB.MP4
SEG_A: FPGA.23 R12.2 R16.2 | length 92.9
  Top Layer w0.254: R12.2 v1(61.976,80.01) ; FPGA.23 86.959,68.623 87.837,67.745 87.837,65.808 v1(89.052,64.592) ; R16.2 v1(110.871,80.01)
  Bottom Layer w0.254: v1(61.976,80.01) 62.064,80.098 78.817,80.098 78.905,80.01 87.306,80.01 87.43,80.134 90.719,80.134 91.348,79.505 93.088,79.505 93.593,80.01 106.074,80.01 ; v1(89.052,64.592) 91.818,67.358 91.818,71.018 89.916,72.919 89.916,74.774 90.932,75.79 92.504,75.79 93.52,74.774 100.838,74.774 106.074,80.01 ; v1(110.871,80.01) 106.074,80.01
SEG_B: FPGA.27 R13.2 R17.2 | length 100.1
  Top Layer w0.254: R13.2 65.093,76.461 v1(65.811,75.743) ; FPGA.27 89.151,71.275 90.449,69.976 v1(90.449,69.266) ; R17.2 v1(113.723,78.435)
  Bottom Layer w0.254: v1(65.811,75.743) 78.2,75.743 78.292,75.651 83.683,75.651 87.935,71.399 87.935,64.008 88.313,63.63 88.389,63.63 ; v1(90.449,69.266) 90.449,66.802 89.916,66.269 89.332,66.269 88.087,65.024 88.087,63.932 88.389,63.63 ; v1(113.723,78.435) 112.522,77.234 112.522,71.552 106.604,65.634 ; 88.389,63.63 89.716,63.63 ; 88.389,63.63 88.9,63.119 89.205,63.119 89.716,63.63 ; 89.716,63.63 91.719,65.634 106.604,65.634 ; 89.716,63.63 89.722,63.63 91.723,65.63 106.601,65.63 106.604,65.634
SEG_C: FPGA.26 R8.1 R20.1 | length 90.3
  Top Layer w0.254: v1(60.249,56.921) 61.214,55.956 R8.1 ; FPGA.26 88.646,70.775 89.474,69.947 89.474,68.58 92.685,65.369 v1(92.685,64.668) ; v1(109.982,54.204) R20.1 v1(109.982,62.205)
  Bottom Layer w0.254: v1(60.249,56.921) 66.494,50.676 97.282,50.676 100.809,54.204 v1(109.982,54.204) ; v1(92.685,64.668) 107.518,64.668 v1(109.982,62.205)
SEG_D: FPGA.28 R7.1 R19.1 | length 82.3
  Top Layer w0.254: R7.1 58.05,55.132 v1(58.953,54.229) ; FPGA.28 89.293,71.775 90.751,70.316 91.454,69.794 91.454,67.848 93.65,65.653 v1(93.65,63.221) ; R19.1 106.299,56.236 107.666,57.602 v1(107.666,60.35)
  Bottom Layer w0.254: v1(58.953,54.229) 58.396,54.786 58.396,59.182 58.928,59.714 72.928,59.714 77.724,54.918 78.791,54.918 80.061,56.188 92.535,56.188 96.698,60.35 ; v1(93.65,63.221) 96.52,60.35 96.698,60.35 ; v1(107.666,60.35) 96.698,60.35
SEG_DP: FPGA.25 R9.1 R21.1 | length 112.5
  Top Layer w0.254: v1(63.094,76.962) 63.094,55.016 64.262,55.016 64.585,55.339 R9.1 v1(66.015,55.626) ; FPGA.25 88.289,70.275 88.289,69.27 88.9,68.658 88.9,67.589 v1(89.256,67.234) ; v1(114.104,53.823) R21.1
  Bottom Layer w0.254: v1(63.094,76.962) 77.889,76.962 78.746,76.105 83.991,76.105 89.256,70.841 v1(89.256,67.234) ; v1(66.015,55.626) 67.631,54.01 80.153,54.01 81.337,55.194 112.732,55.194 v1(114.104,53.823)
SEG_E: FPGA.31 R6.1 R18.1 | length 82.7
  Top Layer w0.254: R6.1 53.837,55.169 v1(59.654,49.352) ; FPGA.31 v1(91.364,73.275) ; v1(96.85,66.777) 96.85,59.665 101.27,55.245 R18.1 102.928,53.327 v1(98.954,49.352)
  Bottom Layer w0.254: v1(59.654,49.352) v1(98.954,49.352) ; v1(91.364,73.275) 91.364,72.263 v1(96.85,66.777)
SEG_F: FPGA.32 R11.2 R15.2 | length 98.5
  Top Layer w0.254: R11.2 55.822,76.352 54.331,76.352 54.331,80.34 v1(57.277,83.287) ; FPGA.32 90.488,73.775 v1(91.542,74.828) ; v1(106.934,76.581) 106.998,76.644 108.13,76.644 R15.2 v1(108.193,84.618)
  Bottom Layer w0.254: v1(57.277,83.287) 61.341,87.351 105.461,87.351 v1(108.193,84.618) ; v1(91.542,74.828) 94.92,71.45 105.664,71.45 107.213,73 107.213,74.513 106.934,74.793 v1(106.934,76.581)
SEG_G: FPGA.34 R10.2 R14.2 | length 66.7
  Top Layer w0.254: R10.2 v1(58.812,80.975) ; FPGA.34 89.151,74.775 92.055,77.68 92.055,79.889 v1(92.634,80.467) ; v1(99.187,80.975) 103.327,76.835 R14.2
  Bottom Layer w0.254: v1(58.812,80.975) 81.458,80.975 81.788,80.645 92.456,80.645 v1(92.634,80.467) v1@92.84,80.674 ; v1@92.84,80.674 93.142,80.975 v1(99.187,80.975) 98.885,80.674 v1@92.84,80.674
SW0: FPGA.46 RW0.2 SW0.2 | length 106.8
  Top Layer w0.254: FPGA.46 82.959,80.242 82.223,80.978 82.223,82.008 83.312,83.097 84.328,83.097 84.865,83.634 84.865,90.58 86.258,91.973 110.82,91.973 112.674,90.119 112.674,50.876 115.316,48.235 RW0.2 115.316,37.617 116.23,36.703 116.23,31.561 SW0.2
SW1: FPGA.47 RW1.2 SW1.2 | length 145.9
  Top Layer w0.254: FPGA.47 82.459,79.013 80.645,80.827 80.645,90.78 82.55,92.685 113.919,92.685 115.214,91.389 115.214,57.379 113.132,55.296 113.132,51.079 116.688,47.523 116.688,30.48 115.57,29.362 110.211,29.362 SW1.2 ; v1(108.135,38.456) RW1.2
  Bottom Layer w0.254: v1(108.135,38.456) 114.808,38.456 116.23,37.033 116.23,32.487 115.316,31.572 110.185,31.572 SW1.2
SW2: FPGA.48 RW2.2 SW2.2 | length 95
  Top Layer w0.254: v1(68.25,46.863) 69.545,48.158 69.545,67.215 68.355,68.405 68.355,69.596 69.088,70.329 69.906,70.329 70.958,71.382 70.958,72.846 72.665,74.553 72.665,79.248 73.427,80.01 80.264,80.01 81.959,78.315 FPGA.48 ; v1(101.658,41.478) RW2.2 101.658,31.692 SW2.2
  Bottom Layer w0.254: v1(68.25,46.863) 96.273,46.863 v1(101.658,41.478)
SW3: FPGA.45 RW3.2 SW3.2 | length 128.2
  Top Layer w0.254: v1(57.531,31.725) 56.007,33.249 56.007,39.116 55.778,39.345 55.778,46.355 57.733,48.309 60.262,48.309 66.98,55.028 66.98,66.046 66.932,66.094 66.932,69.906 67.81,70.783 69.057,70.783 70.05,71.776 70.05,72.793 71.328,74.071 71.328,80.574 v1(73.66,82.906) ; FPGA.45 83.459,80.947 83.636,81.124 83.636,81.895 v1(83.83,82.09) ; RW3.2 95.62,37.451 97.561,35.509 97.561,31.521 SW3.2
  Bottom Layer w0.254: v1(57.531,31.725) 95.275,31.725 SW3.2 ; v1(73.66,82.906) 82.865,82.906 83.681,82.09 v1(83.83,82.09)
SW4: FPGA.2 RW4.2 SW4.2 | length 124
  Top Layer w0.254: v1(80.162,77.845) 80.162,75.885 80.772,75.275 FPGA.2 ; v1(90.264,41.199) 90.747,40.716 RW4.2 90.747,36.837 91.465,36.119 91.465,31.521 SW4.2
  Bottom Layer w0.254: v1(80.162,77.845) 78.363,79.644 65.877,79.644 65.253,79.019 54.254,79.019 49.428,74.193 49.428,44.831 57.379,36.881 85.946,36.881 v1(90.264,41.199)
SW5: FPGA.4 RW5.2 SW5.2 | length 93.7
  Top Layer w0.254: v1(77.749,74.778) 78.252,74.275 FPGA.4 ; v1(81.331,40.132) RW5.2@83.16,40.132 ; RW5.2 RW5.2@83.16,40.132 ; SW5.2 84.201,31.318 83.16,32.36 RW5.2@83.16,40.132
  Bottom Layer w0.254: v1(77.749,74.778) 77.575,74.952 66.726,74.952 66.238,74.464 66.238,72.763 59.642,66.167 54.458,66.167 53.315,65.024 53.315,47.862 61.045,40.132 v1(81.331,40.132)
SW6: FPGA.3 RW6.2 SW6.2 | length 68.5
  Top Layer w0.254: v1(74.473,78.207) 73.965,77.699 73.965,72.847 71.866,70.748 71.866,68.408 71.349,67.891 71.349,43.713 71.374,43.688 71.374,42.443 74.752,42.443 76.378,44.069 78.613,44.069 78.613,41.91 77.401,40.698 RW6.2 77.401,37.414 79.019,35.796 79.019,31.521 SW6.2 ; v1(76.937,78.207) 80.368,74.775 FPGA.3
  Bottom Layer w0.254: v1(74.473,78.207) v1(76.937,78.207)
SW7: FPGA.6 RW7.2 SW7.2 | length 54.8
  Top Layer w0.254: v1(69.682,68.859) 70.333,68.209 70.333,47.6 69.443,46.71 69.443,41.358 70.542,40.259 RW7.2 71.305,37.414 72.923,35.796 72.923,31.521 SW7.2 ; v1(77.064,71.349) 78.99,73.275 FPGA.6
  Bottom Layer w0.254: v1(69.682,68.859) 74.574,68.859 v1(77.064,71.349)
SW8: FPGA.9 RW8.2 SW8.2 | length 57.2
  Top Layer w0.254: SW8.2 66.954,31.521 66.954,36.119 65.982,37.091 RW8.2 65.982,41.173 64.516,42.639 64.516,44.323 63.983,44.856 63.983,50.19 67.462,53.67 67.462,66.243 v1(67.894,66.675) ; v1(76.505,66.116) 76.505,68.748 79.532,71.775 FPGA.9
  Bottom Layer w0.254: v1(67.894,66.675) 68.605,65.964 76.352,65.964 v1(76.505,66.116)
SW9: FPGA.10 RW9.2 SW9.2 | length 68.2
  Top Layer w0.254: SW9.2 60.985,31.521 60.985,35.828 59.298,37.516 RW9.2 59.298,40.894 59.654,41.25 v1(61.722,41.25) ; v1(78.946,69.774) 80.447,71.275 FPGA.10
  Bottom Layer w0.254: v1(61.722,41.25) 55.855,47.117 55.855,64.643 56.896,65.684 61.9,65.684 64.11,67.894 75.489,67.894 77.368,69.774 v1(78.946,69.774)
SW10: FPGA.11 RW10.2 SW10.2 | length 104.9
  Top Layer w0.254: SW10.2 55.016,31.521 55.016,35.745 53.144,37.617 RW10.2 53.144,66.65 55.397,68.903 55.397,74.6 53.873,76.124 53.873,83.312 55.423,84.861 69.037,84.861 69.545,84.353 69.545,76.2 67.412,74.066 v1(67.412,73.99) ; v1(80.162,68.351) 80.594,68.783 80.594,70.775 FPGA.11
  Bottom Layer w0.254: v1(67.412,73.99) 67.589,73.812 79.952,73.812 80.162,73.602 v1(80.162,68.351)
Transistor_BASE_1: B1.3 B1.8 Q1.3 | length 56.7
  Top Layer w0.254: B1.3 B1.8 ; Q1.3 96.429,51.882 v1(96.672,51.638)
  Bottom Layer w0.254: B1.3 60.274,58.674 67.108,51.84 96.471,51.84 v1(96.672,51.638)
Transistor_BASE_2: B2.3 B2.8 Q2.3 | length 56.6
  Top Layer w0.254: Q2.3 v1(73.041,55.753) ; B2.3 B2.8
  Bottom Layer w0.254: v1(73.041,55.753) 76.232,55.753 77.521,54.464 78.994,54.464 80.264,55.734 106.153,55.734 B2.3
USB_5V: 1.2V.3 3.3V.3 5V.1 C9.1 C10.1 C11.1 USB.1 | length 143.3
  Top Layer w0.254: USB.1 50.546,73.609 50.546,78.588 47.168,81.966 47.168,84.607 48.916,86.356 3.3V.3 69.121,86.356 70.162,85.315 C10.1 70.162,83.926 ; v1(66.015,60.935) 66.015,70.01 67.298,71.293 68.601,71.293 69.542,72.234 69.542,72.971 70.162,73.591 70.162,83.926 ; v1(71.425,82.664) 70.162,83.926 ; v1(74.016,60.935) 74.313,60.637 C9.1 ; C11.1 86.926,82.086 v1(87.376,81.636) ; 1.2V.3 108.327,86.229 5V.1
  Bottom Layer w0.254: v1(66.015,60.935) v1(74.016,60.935) ; v1(71.425,82.664) 72.297,81.791 81.41,81.791 82.074,81.128 85.317,81.128 85.673,81.484 ; v1(87.376,81.636) 85.825,81.636 85.673,81.484 ; 5V.1 109.626,86.716 109.626,83.312 108.839,82.525 96.317,82.525 95.939,82.147 90.224,82.147 88.652,83.718 85.268,83.718 84.861,83.312 84.861,82.296 85.673,81.484
VCC_1.2V: 1.2V.2 1.2V.4 C1.1 C5.1 CB_2.1 FPGA.5 FPGA.30 | length 110.4
  Top Layer w0.254: v1(68.072,72.375) 67.419,73.028 66.802,73.028 66.45,73.381 66.45,74.676 68.58,76.806 v1(68.58,83.896) ; v1(73.901,70.714) 74.822,69.792 C5.1 ; v1(76.987,72.822) 77.941,73.775 FPGA.5 ; CB_2.1 89.246,88.478 ; FPGA.30 90.293,72.775 90.932,72.136 91.948,72.136 92.685,72.873 92.685,75.616 93.542,76.473 93.542,79.051 94.126,79.635 94.126,84.099 93.193,85.033 93.193,85.344 ; v1(90.348,85.979) 90.348,87.376 89.246,88.478 ; C1.1 94.996,69.723 95.301,70.028 95.301,81.236 96.212,82.147 96.212,83.617 95.758,84.071 94.466,84.071 93.193,85.344 ; 1.2V.4 1.2V.2 93.472,88.519 ; 89.246,88.478 90.754,88.478 90.795,88.519 93.472,88.519 ; 93.193,85.344 93.193,88.24 93.472,88.519
  Bottom Layer w0.254: v1(68.072,72.375) 69.733,70.714 v1(73.901,70.714) 76.009,72.822 v1(76.987,72.822) ; v1(68.58,83.896) 70.89,83.896 72.973,85.979 v1(90.348,85.979)
VCC_3.3V: 3.3V.2 3.3V.4 BTNC.2 BTND.2 C2.1 C3.1 C4.1 C6.1 C7.1 C8.1 C_CLK.1 C_F.1 CB_1.1 CLK.1 FPGA.1 FPGA.8 FPGA.13 FPGA.22 FPGA.24 FPGA.29 FPGA.33 R_BTNC.1 R_BTND.1 R_F2.2 R_F.2 R_RS.1 R_RS.2 RESET.2 RW0.1 RW1.1 RW2.1 RW3.1 RW4.1 RW5.1 RW6.1 RW7.1 RW8.1 RW9.1 RW10.1 | length 510.9
  Top Layer w0.254: R_RS.1 44.958,40.513 ; RESET.2 46.126,31.434 46.126,34.722 ; R_BTND.1 46.551,94.825 46.228,95.148 45.436,95.148 43.76,93.472 BTND.2 ; RW10.1 54.044,37.625 55.474,36.195 55.474,31.902 58.141,29.235 ; RW9.1 61.29,40.386 61.417,40.259 63.754,40.259 ; RW8.1 RW8.1@64.872,40.259 ; v1(74.143,84.861) 72.873,84.861 70.427,87.307 CB_1.1 ; v1(74.854,38.329) 73.381,39.802 ; C6.1 75.311,71.12 75.921,70.51 ; R_F.2 75.946,59.639 76.556,60.249 ; v1(78.638,38.329) 78.301,38.666 RW6.1 78.301,40.64 78.86,41.199 83.515,41.199 84.074,40.64 RW5.1 ; C_CLK.1 79.052,91.363 77.783,90.094 CLK.1 71.611,89.535 CB_1.1 ; FPGA.8 79.39,72.275 77.499,70.383 75.927,70.383 ; FPGA.1 81.128,75.775 81.128,78.504 80.462,79.17 ; FPGA.13 81.959,67.614 81.28,66.935 79.066,66.935 77.285,65.154 75.689,65.154 75.311,65.532 ; FPGA.22 86.459,68.077 87.383,67.153 87.383,64.008 87.761,63.63 89.456,63.63 90.17,64.345 90.17,65.049 ; FPGA.24 87.459,69.063 88.291,68.231 88.291,66.548 88.567,66.272 88.948,66.272 90.17,65.049 ; FPGA.29 89.435,72.275 90.94,70.77 92.501,70.77 93.167,70.104 ; FPGA.33 89.293,74.275 92.634,77.616 92.634,78.921 93.596,79.883 93.596,83.439 92.456,84.579 v1(91.748,84.579) ; RW4.1 87.071,40.005 86.944,40.132 RW5.1 ; C4.1 C3.1 93.624,74.861 93.624,71.882 93.889,71.617 C2.1 94.234,71.171 93.574,71.171 93.167,70.764 93.167,70.104 ; R_F2.2 94.615,59.512 ; v1(96.85,38.075) 96.52,38.405 RW3.1 96.52,40.284 96.012,40.792 94.971,40.792 92.964,38.786 92.964,28.169 91.44,26.645 88.392,26.645 86.944,28.092 86.944,36.576 84.074,39.446 RW5.1 ; v1(103.988,40.183) 103.81,40.005 RW2.1 102.558,35.77 106.604,31.725 109.347,31.725 110.134,32.512 110.134,39.624 109.372,40.386 ; RW1.1 109.372,40.386 ; RW0.1 109.372,40.386 ; BTND.2 42.367,88.269 42.367,59.764 BTNC.2 44.958,57.173 R_BTNC.1 44.958,40.513 ; BTND.2 44.852,88.57 52.4,88.57 52.476,88.646 3.3V.2 3.3V.4 66.675,88.646 66.97,88.351 CB_1.1 ; 44.958,40.513 R_RS.2 45.745,40.513 46.126,40.132 46.126,34.722 ; 46.126,34.722 51.613,29.235 58.141,29.235 ; 58.141,29.235 60.96,29.235 62.103,30.378 62.103,38.608 63.754,40.259 ; 63.754,40.259 RW8.1@64.872,40.259 ; RW8.1@64.872,40.259 64.872,29.972 65.405,29.439 72.898,29.439 73.381,29.921 73.381,39.802 ; 73.381,39.802 72.923,40.259 RW7.1 72.205,40.622 71.675,41.151 71.12,41.151 69.897,42.374 69.897,43.907 70.891,44.901 70.891,70.051 71.412,70.571 71.412,71.557 73.508,73.653 73.508,78.764 73.914,79.17 76.181,79.17 ; 75.311,65.532 75.311,65.119 76.556,63.875 76.556,60.249 ; 75.311,65.532 75.311,67.083 75.921,67.692 ; 75.921,67.692 75.921,70.51 ; 75.921,67.692 75.927,67.699 75.927,70.383 ; 75.921,70.51 75.921,74.56 C7.1 C8.1 75.921,76.258 75.921,78.91 76.181,79.17 ; 75.921,70.51 75.927,70.504 75.927,70.383 ; 76.181,79.17 76.2,79.19 80.442,79.19 80.462,79.17 ; 76.181,79.17 80.462,79.17 ; 76.556,60.249 78.232,61.925 83.795,61.925 84.303,61.417 84.303,50.267 85.344,49.225 87.655,49.225 89.23,50.8 89.23,51.765 92.202,54.737 92.202,58.623 93.853,60.274 ; 90.17,65.049 92.964,62.255 94.183,62.255 94.463,61.976 94.463,60.96 94.14,60.637 C_F.1 93.853,60.274 ; 93.167,70.104 93.167,66.827 94.615,65.38 94.615,59.512 ; 93.853,60.274 94.615,59.512
  Bottom Layer w0.254: v1(74.143,84.861) 74.701,85.42 89.027,85.42 89.868,84.579 v1(91.748,84.579) ; v1(74.854,38.329) v1(78.638,38.329) ; v1(96.85,38.075) 101.879,38.075 v1(103.988,40.183)
pads on no net: USB.MH1 USB.MH2

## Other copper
Multi-Layer:
  text "Team_A3" at 118.745,81.788 h5 r270

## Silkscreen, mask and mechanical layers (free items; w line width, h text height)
Mechanical 1:
  lines w0.254: 40.132,23.368 129.413,23.368 129.413,89.916 119.38,99.949 40.132,99.949 40.132,34.036 40.132,23.368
